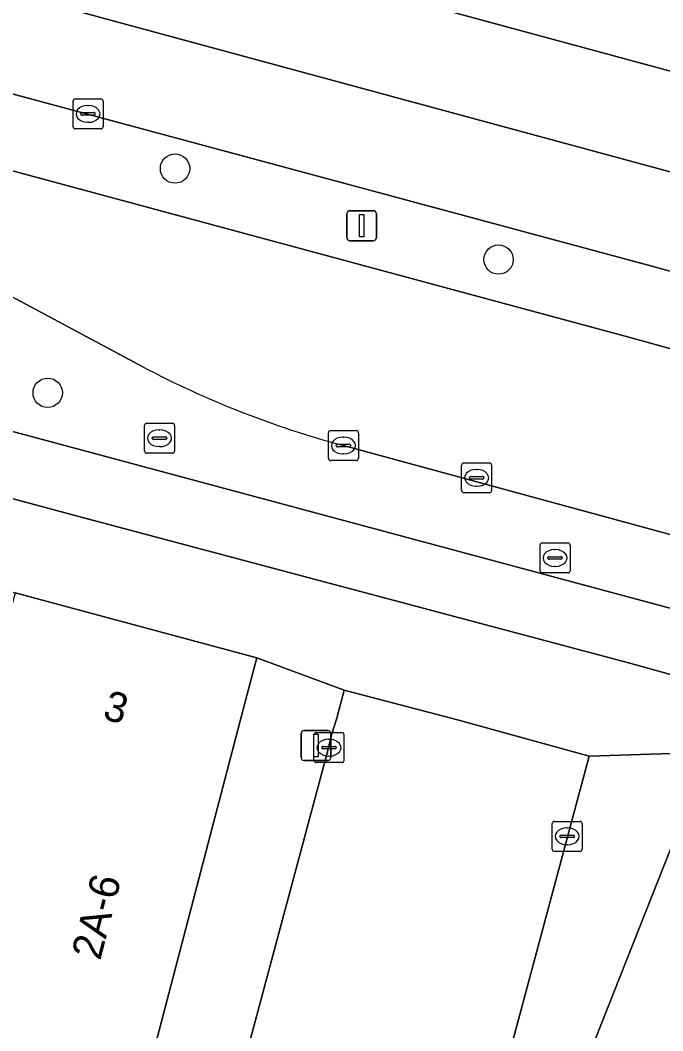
# Model space of a CAD drawing. Extents: x 160675 to 161153, y 383241 to 383714.
# Drawn here: x 160849.57 to 160871.01, y 383553.38 to 383587.08 of the extents above; entities that cross this region are included whole.
import ezdxf

# ---------------------------------------------------------------- set-up
doc = ezdxf.new("R2010")
doc.units = 0
for name, color, linetype in [('IMGEO_Berm_groen', 7, 'Continuous'), ('IMGEO_Berm_open', 7, 'Continuous'), ('IMGEO_Boom', 7, 'Continuous'), ('IMGEO_Fietspad_gesloten', 7, 'Continuous'), ('IMGEO_Kolk', 7, 'Continuous'), ('IMGEO_Lichtmast', 7, 'Continuous'), ('IMGEO_OVBaan_gesloten', 7, 'Continuous'), ('IMGEO_Pand', 7, 'Continuous'), ('IMGEO_Pand_nummerreeks', 7, 'Continuous'), ('IMGEO_Rijbaan_lokaal_gesloten', 7, 'Continuous'), ('IMGEO_Rijbaan_lokaal_open', 7, 'Continuous'), ('IMGEO_Rioolput', 7, 'Continuous'), ('IMGEO_Voetpad_open', 7, 'Continuous')]:
    doc.layers.add(name, color=color, linetype=linetype)

msp = doc.modelspace()

# ---------------------------------------------------------------- linework, layer by layer
at = {"layer": 'IMGEO_Berm_groen'}
for points in [[(160870.684, 383578.867), (160797.835, 383598.49), (160797.171, 383596.125), (160869.874, 383576.512), (160913.282, 383564.496)], [(160946.568, 383557.927), (160870.684, 383578.867)]]:
    msp.add_lwpolyline(points, dxfattribs=at)
at = {"layer": 'IMGEO_Berm_open'}
for points in [[(160753.356, 383599.164), (160754.374, 383598.874), (160872.54, 383567.128), (160873.601, 383566.834), (160874.194, 383569.11), (160871.092, 383569.968), (160860.355, 383572.895)], [(160853.656, 383575.522), (160848.337, 383578.365), (160844.949, 383579.673)]]:
    msp.add_lwpolyline(points, dxfattribs=at)
msp.add_arc((160868.647, 383603.896), 32.091, 242.1503, 255.0247, dxfattribs=at)
at = {"layer": 'IMGEO_Boom'}
for centre in [(160854.735, 383582.13), (160865.529, 383579.098), (160850.486, 383574.652)]:
    msp.add_circle(centre, 0.489, dxfattribs=at)
at = {"layer": 'IMGEO_Fietspad_gesloten'}
for points in [[(160741.54, 383600.127), (160851.652, 383570.489), (160869.912, 383565.633), (160904.417, 383556.04)], [(160904.814, 383558.169), (160877.012, 383565.887), (160875.567, 383566.288), (160873.601, 383566.834), (160872.54, 383567.128), (160754.374, 383598.874)]]:
    msp.add_lwpolyline(points, dxfattribs=at)
at = {"layer": 'IMGEO_Kolk'}
for p, q in [((160851.331, 383583.529), (160851.331, 383584.381)), ((160851.406, 383584.455), (160852.258, 383584.455)), ((160851.819, 383584.235), (160851.844, 383584.235)), ((160852.332, 383584.381), (160852.332, 383583.529)), ((160851.59, 383583.949), (160851.59, 383583.961)), ((160852.028, 383583.912), (160851.63, 383583.912)), ((160851.633, 383583.998), (160852.031, 383583.998)), ((160852.074, 383583.961), (160852.074, 383583.949)), ((160851.842, 383583.675), (160851.817, 383583.675)), ((160852.258, 383583.455), (160851.406, 383583.455)), ((160853.718, 383572.712), (160853.718, 383573.564)), ((160853.793, 383573.638), (160854.645, 383573.638)), ((160854.206, 383573.418), (160854.231, 383573.418)), ((160854.719, 383573.564), (160854.719, 383572.712)), ((160859.929, 383573.394), (160860.781, 383573.394)), ((160853.977, 383573.132), (160853.977, 383573.144)), ((160854.415, 383573.095), (160854.017, 383573.095)), ((160854.02, 383573.181), (160854.418, 383573.181)), ((160854.461, 383573.144), (160854.461, 383573.132)), ((160859.854, 383572.468), (160859.854, 383573.32)), ((160860.342, 383573.174), (160860.367, 383573.174)), ((160860.855, 383573.32), (160860.855, 383572.468)), ((160854.229, 383572.858), (160854.204, 383572.858)), ((160860.113, 383572.888), (160860.113, 383572.9)), ((160860.551, 383572.851), (160860.153, 383572.851)), ((160860.156, 383572.937), (160860.554, 383572.937)), ((160860.597, 383572.9), (160860.597, 383572.888)), ((160854.645, 383572.638), (160853.793, 383572.638)), ((160860.781, 383572.394), (160859.929, 383572.394)), ((160860.365, 383572.614), (160860.34, 383572.614)), ((160859.447, 383563.319), (160860.299, 383563.319)), ((160859.372, 383562.393), (160859.372, 383563.245)), ((160859.86, 383563.099), (160859.885, 383563.099)), ((160860.373, 383563.245), (160860.373, 383562.393)), ((160859.631, 383562.813), (160859.631, 383562.825)), ((160860.069, 383562.776), (160859.671, 383562.776)), ((160859.674, 383562.862), (160860.072, 383562.862)), ((160860.115, 383562.825), (160860.115, 383562.813)), ((160860.299, 383562.319), (160859.447, 383562.319)), ((160859.883, 383562.539), (160859.858, 383562.539)), ((160867.319, 383559.434), (160867.319, 383560.286)), ((160867.394, 383560.36), (160868.246, 383560.36)), ((160868.32, 383560.286), (160868.32, 383559.434)), ((160867.621, 383559.903), (160868.019, 383559.903)), ((160867.807, 383560.14), (160867.832, 383560.14)), ((160867.578, 383559.854), (160867.578, 383559.866)), ((160868.016, 383559.817), (160867.618, 383559.817)), ((160867.83, 383559.58), (160867.805, 383559.58)), ((160868.062, 383559.866), (160868.062, 383559.854)), ((160868.246, 383559.36), (160867.394, 383559.36))]:
    msp.add_line(p, q, dxfattribs=at)
for points in [[(160851.331, 383583.529), (160851.331, 383584.381)], [(160851.406, 383584.455), (160852.258, 383584.455)], [(160852.332, 383584.381), (160852.332, 383583.529)], [(160852.258, 383583.455), (160851.406, 383583.455)], [(160853.718, 383572.712), (160853.718, 383573.564)], [(160853.793, 383573.638), (160854.645, 383573.638)], [(160854.719, 383573.564), (160854.719, 383572.712)], [(160859.929, 383573.394), (160860.781, 383573.394)], [(160859.854, 383572.468), (160859.854, 383573.32)], [(160860.855, 383573.32), (160860.855, 383572.468)], [(160854.645, 383572.638), (160853.793, 383572.638)], [(160860.781, 383572.394), (160859.929, 383572.394)], [(160859.447, 383563.319), (160860.299, 383563.319)], [(160859.372, 383562.393), (160859.372, 383563.245)], [(160860.373, 383563.245), (160860.373, 383562.393)], [(160860.299, 383562.319), (160859.447, 383562.319)], [(160867.319, 383559.434), (160867.319, 383560.286)], [(160867.394, 383560.36), (160868.246, 383560.36)], [(160868.32, 383560.286), (160868.32, 383559.434)], [(160868.246, 383559.36), (160867.394, 383559.36)]]:
    msp.add_lwpolyline(points, dxfattribs=at)
for centre, radius, start, end in [((160851.408, 383584.379), 0.0765, 91.552, 178.448), ((160851.408, 383584.379), 0.0765, 91.552, 178.448), ((160852.256, 383584.379), 0.0765, 1.552, 88.448), ((160852.256, 383584.379), 0.0765, 1.552, 88.448), ((160851.63, 383583.958), 0.0403, 85.8775, 175.7526), ((160851.627, 383583.948), 0.0366, 178.938, 274.7102), ((160852.031, 383583.955), 0.043, 264.8664, 352.4533), ((160852.035, 383583.96), 0.0386, 1.7309, 96.639), ((160851.408, 383583.531), 0.0765, 181.552, 268.448), ((160851.408, 383583.531), 0.0765, 181.552, 268.448), ((160852.256, 383583.531), 0.0765, 271.552, 358.448), ((160852.256, 383583.531), 0.0765, 271.552, 358.448), ((160853.795, 383573.562), 0.0765, 91.552, 178.448), ((160853.795, 383573.562), 0.0765, 91.552, 178.448), ((160854.643, 383573.562), 0.0765, 1.552, 88.448), ((160854.643, 383573.562), 0.0765, 1.552, 88.448), ((160859.931, 383573.318), 0.0765, 91.552, 178.448), ((160859.931, 383573.318), 0.0765, 91.552, 178.448), ((160860.779, 383573.318), 0.0765, 1.552, 88.448), ((160860.779, 383573.318), 0.0765, 1.552, 88.448), ((160854.017, 383573.141), 0.0403, 85.8775, 175.7526), ((160854.014, 383573.131), 0.0366, 178.938, 274.7102), ((160854.418, 383573.138), 0.043, 264.8664, 352.4533), ((160854.422, 383573.143), 0.0386, 1.7309, 96.639), ((160853.795, 383572.714), 0.0765, 181.552, 268.448), ((160853.795, 383572.714), 0.0765, 181.552, 268.448), ((160854.643, 383572.714), 0.0765, 271.552, 358.448), ((160854.643, 383572.714), 0.0765, 271.552, 358.448), ((160860.153, 383572.897), 0.0403, 85.8775, 175.7526), ((160860.15, 383572.887), 0.0366, 178.938, 274.7102), ((160860.554, 383572.894), 0.043, 264.8664, 352.4533), ((160860.558, 383572.899), 0.0386, 1.7309, 96.639), ((160859.931, 383572.47), 0.0765, 181.552, 268.448), ((160859.931, 383572.47), 0.0765, 181.552, 268.448), ((160860.779, 383572.47), 0.0765, 271.552, 358.448), ((160860.779, 383572.47), 0.0765, 271.552, 358.448), ((160859.449, 383563.243), 0.0765, 91.552, 178.448), ((160859.449, 383563.243), 0.0765, 91.552, 178.448), ((160860.297, 383563.243), 0.0765, 1.552, 88.448), ((160860.297, 383563.243), 0.0765, 1.552, 88.448), ((160859.671, 383562.822), 0.0403, 85.8775, 175.7526), ((160859.668, 383562.812), 0.0366, 178.938, 274.7102), ((160860.072, 383562.819), 0.043, 264.8664, 352.4533), ((160860.076, 383562.824), 0.0386, 1.7309, 96.639), ((160859.449, 383562.395), 0.0765, 181.552, 268.448), ((160859.449, 383562.395), 0.0765, 181.552, 268.448), ((160860.297, 383562.395), 0.0765, 271.552, 358.448), ((160860.297, 383562.395), 0.0765, 271.552, 358.448), ((160867.396, 383560.284), 0.0765, 91.552, 178.448), ((160867.396, 383560.284), 0.0765, 91.552, 178.448), ((160868.244, 383560.284), 0.0765, 1.552, 88.448), ((160868.244, 383560.284), 0.0765, 1.552, 88.448), ((160867.618, 383559.863), 0.0403, 85.8775, 175.7526), ((160868.023, 383559.865), 0.0386, 1.7309, 96.639), ((160867.615, 383559.853), 0.0366, 178.938, 274.7102), ((160868.019, 383559.86), 0.043, 264.8664, 352.4533), ((160867.396, 383559.436), 0.0765, 181.552, 268.448), ((160867.396, 383559.436), 0.0765, 181.552, 268.448), ((160868.244, 383559.436), 0.0765, 271.552, 358.448), ((160868.244, 383559.436), 0.0765, 271.552, 358.448)]:
    msp.add_arc(centre, radius, start, end, dxfattribs=at)
for centre, major_axis, ratio, start_param, end_param in [((160851.818, 383583.955), (-0.387, 0.002), 0.722429, 4.712389, 7.853982), ((160851.843, 383583.955), (-0.39, 0.002), 0.717154, 1.570796, 4.712389), ((160854.205, 383573.138), (-0.387, 0.002), 0.722429, 4.712389, 7.853982), ((160854.23, 383573.138), (-0.39, 0.002), 0.717154, 1.570796, 4.712389), ((160860.341, 383572.894), (-0.387, 0.002), 0.722429, 4.712389, 7.853982), ((160860.366, 383572.894), (-0.39, 0.002), 0.717154, 1.570796, 4.712389), ((160859.859, 383562.819), (-0.387, 0.002), 0.722429, 4.712389, 7.853982), ((160859.884, 383562.819), (-0.39, 0.002), 0.717154, 1.570796, 4.712389), ((160867.806, 383559.86), (-0.387, 0.002), 0.722429, 4.712389, 7.853982), ((160867.831, 383559.86), (-0.39, 0.002), 0.717154, 1.570796, 4.712389)]:
    msp.add_ellipse(centre, major_axis=major_axis, ratio=ratio, start_param=start_param, end_param=end_param, dxfattribs=at)
at = {"layer": 'IMGEO_Lichtmast'}
for p, q in [((160860.468, 383579.826), (160860.468, 383580.626)), ((160860.468, 383580.626), (160860.468, 383579.826)), ((160860.568, 383580.726), (160861.358, 383580.726)), ((160861.358, 383580.726), (160860.568, 383580.726)), ((160861.458, 383580.626), (160861.458, 383579.826)), ((160861.458, 383579.826), (160861.458, 383580.626)), ((160861.358, 383579.726), (160860.568, 383579.726)), ((160860.568, 383579.726), (160861.358, 383579.726)), ((160858.942, 383562.49), (160858.942, 383563.29)), ((160858.942, 383563.29), (160858.942, 383562.49)), ((160859.042, 383563.39), (160859.832, 383563.39)), ((160859.832, 383563.39), (160859.042, 383563.39)), ((160859.932, 383563.29), (160859.932, 383562.49)), ((160859.932, 383562.49), (160859.932, 383563.29)), ((160859.832, 383562.39), (160859.042, 383562.39)), ((160859.042, 383562.39), (160859.832, 383562.39))]:
    msp.add_line(p, q, dxfattribs=at)
for points in [[(160860.888, 383580.601), (160861.038, 383580.601), (160861.038, 383579.851), (160860.888, 383579.851), (160860.888, 383580.601)], [(160859.362, 383563.265), (160859.512, 383563.265), (160859.512, 383562.515), (160859.362, 383562.515), (160859.362, 383563.265)]]:
    msp.add_lwpolyline(points, dxfattribs=at)
for centre, start, end in [((160860.568, 383580.626), 90, 180), ((160860.568, 383580.626), 90, 180), ((160861.358, 383580.626), 0, 90), ((160861.358, 383580.626), 360, 90), ((160860.568, 383579.826), 180, 270), ((160860.568, 383579.826), 180, 270), ((160861.358, 383579.826), 270, 0), ((160861.358, 383579.826), 270, 0), ((160859.042, 383563.29), 90, 180), ((160859.042, 383563.29), 90, 180), ((160859.832, 383563.29), 0, 90), ((160859.832, 383563.29), 360, 90), ((160859.042, 383562.49), 180, 270), ((160859.042, 383562.49), 180, 270), ((160859.832, 383562.49), 270, 0), ((160859.832, 383562.49), 270, 0)]:
    msp.add_arc(centre, 0.1, start, end, dxfattribs=at)
at = {"layer": 'IMGEO_OVBaan_gesloten'}
for points in [[(160760.567, 383616.024), (160759.368, 383616.453), (160756.884, 383613.99), (160761.763, 383612.059), (160766.781, 383610.37), (160770.415, 383609.332), (160774.938, 383608.123), (160890.249, 383576.873), (160942.076, 383562.592), (160950.815, 383560.255), (160956.785, 383559.216), (160962.841, 383558.697), (160968.725, 383558.524), (160975.387, 383558.61), (160977.148, 383558.794), (160977.505, 383562.304), (160973.835, 383561.901)], [(160973.434, 383555.262), (160976.812, 383555.49), (160977.148, 383558.794), (160975.387, 383558.61), (160968.725, 383558.524), (160962.841, 383558.697), (160956.785, 383559.216), (160950.815, 383560.255), (160942.076, 383562.592), (160890.249, 383576.873), (160774.938, 383608.123), (160770.415, 383609.332), (160766.781, 383610.37), (160761.763, 383612.059), (160756.884, 383613.99)], [(160949.177, 383564.05), (160942.127, 383565.955), (160880.388, 383583.018), (160880.346, 383582.924), (160861.613, 383588.006), (160783.094, 383609.33)], [(160765.95, 383607.15), (160797.835, 383598.49), (160870.684, 383578.867), (160946.568, 383557.927)]]:
    msp.add_lwpolyline(points, dxfattribs=at)
at = {"layer": 'IMGEO_Pand'}
msp.add_lwpolyline([(160857.143, 383564.601), (160857.461, 383565.816), (160849.404, 383567.986), (160845.929, 383555.083), (160845.578, 383553.78), (160844.825, 383550.984), (160843.174, 383544.853), (160849.994, 383543.081), (160850.028, 383543.072), (160850.324, 383542.913), (160852.917, 383548.465)], close=True, dxfattribs=at)
at = {"layer": 'IMGEO_Rijbaan_lokaal_gesloten'}
for points in [[(160784.127, 383609.308), (160809.68, 383602.419), (160845.226, 383592.848), (160861.742, 383588.359), (160861.613, 383588.006), (160880.346, 383582.924), (160880.388, 383583.018), (160880.432, 383583.23), (160883.368, 383582.463), (160942.181, 383566.161)], [(160748.774, 383605.431), (160752.694, 383604.486), (160754.68, 383603.938), (160760.442, 383602.399), (160762.407, 383601.874), (160786.733, 383595.326), (160792.524, 383593.731), (160819.386, 383586.497), (160826.28, 383584.667), (160844.949, 383579.673), (160848.337, 383578.365), (160853.656, 383575.522)], [(160869.874, 383576.512), (160797.171, 383596.125), (160768.531, 383603.87)], [(160913.282, 383564.496), (160869.874, 383576.512)], [(160860.355, 383572.895), (160871.092, 383569.968), (160874.194, 383569.11), (160876.194, 383568.556), (160877.64, 383568.157), (160899.725, 383562.047), (160911.387, 383558.791)]]:
    msp.add_lwpolyline(points, dxfattribs=at)
msp.add_arc((160868.647, 383603.896), 32.091, 242.1503, 255.0247, dxfattribs=at)
at = {"layer": 'IMGEO_Rijbaan_lokaal_open'}
msp.add_lwpolyline([(160862.182, 383538.869), (160865.424, 383550.899), (160868.559, 383562.537), (160864.165, 383563.744), (160860.38, 383564.733), (160860.129, 383563.804), (160859.957, 383563.251), (160859.831, 383562.723), (160856.929, 383551.908)], dxfattribs=at)
at = {"layer": 'IMGEO_Rioolput'}
for p, q in [((160864.299, 383571.392), (160864.299, 383572.244)), ((160864.374, 383572.318), (160865.226, 383572.318)), ((160864.787, 383572.098), (160864.812, 383572.098)), ((160865.3, 383572.244), (160865.3, 383571.392)), ((160864.558, 383571.812), (160864.558, 383571.824)), ((160864.996, 383571.775), (160864.598, 383571.775)), ((160864.601, 383571.861), (160864.999, 383571.861)), ((160865.042, 383571.824), (160865.042, 383571.812)), ((160864.81, 383571.538), (160864.785, 383571.538)), ((160865.226, 383571.318), (160864.374, 383571.318)), ((160866.914, 383568.719), (160866.914, 383569.571)), ((160866.989, 383569.645), (160867.841, 383569.645)), ((160867.402, 383569.425), (160867.427, 383569.425)), ((160867.915, 383569.571), (160867.915, 383568.719)), ((160867.173, 383569.139), (160867.173, 383569.151)), ((160867.611, 383569.102), (160867.213, 383569.102)), ((160867.216, 383569.188), (160867.614, 383569.188)), ((160867.657, 383569.151), (160867.657, 383569.139)), ((160867.425, 383568.865), (160867.4, 383568.865)), ((160867.841, 383568.645), (160866.989, 383568.645))]:
    msp.add_line(p, q, dxfattribs=at)
for points in [[(160864.299, 383571.392), (160864.299, 383572.244)], [(160864.374, 383572.318), (160865.226, 383572.318)], [(160865.3, 383572.244), (160865.3, 383571.392)], [(160865.226, 383571.318), (160864.374, 383571.318)], [(160866.914, 383568.719), (160866.914, 383569.571)], [(160866.989, 383569.645), (160867.841, 383569.645)], [(160867.915, 383569.571), (160867.915, 383568.719)], [(160867.841, 383568.645), (160866.989, 383568.645)]]:
    msp.add_lwpolyline(points, dxfattribs=at)
for centre, radius, start, end in [((160864.376, 383572.242), 0.0765, 91.552, 178.448), ((160864.376, 383572.242), 0.0765, 91.552, 178.448), ((160865.224, 383572.242), 0.0765, 1.552, 88.448), ((160865.224, 383572.242), 0.0765, 1.552, 88.448), ((160864.598, 383571.821), 0.0403, 85.8775, 175.7526), ((160864.595, 383571.811), 0.0366, 178.938, 274.7102), ((160864.999, 383571.818), 0.043, 264.8664, 352.4533), ((160865.003, 383571.823), 0.0386, 1.7309, 96.639), ((160864.376, 383571.394), 0.0765, 181.552, 268.448), ((160864.376, 383571.394), 0.0765, 181.552, 268.448), ((160865.224, 383571.394), 0.0765, 271.552, 358.448), ((160865.224, 383571.394), 0.0765, 271.552, 358.448), ((160866.991, 383569.569), 0.0765, 91.552, 178.448), ((160866.991, 383569.569), 0.0765, 91.552, 178.448), ((160867.839, 383569.569), 0.0765, 1.552, 88.448), ((160867.839, 383569.569), 0.0765, 1.552, 88.448), ((160867.213, 383569.148), 0.0403, 85.8775, 175.7526), ((160867.21, 383569.138), 0.0366, 178.938, 274.7102), ((160867.614, 383569.145), 0.043, 264.8664, 352.4533), ((160867.618, 383569.15), 0.0386, 1.7309, 96.639), ((160866.991, 383568.721), 0.0765, 181.552, 268.448), ((160866.991, 383568.721), 0.0765, 181.552, 268.448), ((160867.839, 383568.721), 0.0765, 271.552, 358.448), ((160867.839, 383568.721), 0.0765, 271.552, 358.448)]:
    msp.add_arc(centre, radius, start, end, dxfattribs=at)
for centre, major_axis, ratio, start_param, end_param in [((160864.786, 383571.818), (-0.387, 0.002), 0.722429, 4.712389, 7.853982), ((160864.811, 383571.818), (-0.39, 0.002), 0.717154, 1.570796, 4.712389), ((160867.401, 383569.145), (-0.387, 0.002), 0.722429, 4.712389, 7.853982), ((160867.426, 383569.145), (-0.39, 0.002), 0.717154, 1.570796, 4.712389)]:
    msp.add_ellipse(centre, major_axis=major_axis, ratio=ratio, start_param=start_param, end_param=end_param, dxfattribs=at)
at = {"layer": 'IMGEO_Voetpad_open'}
for points in [[(160851.652, 383570.489), (160741.54, 383600.127)], [(160818.982, 383576.181), (160825.065, 383574.542), (160831.149, 383572.903), (160837.232, 383571.265), (160843.316, 383569.626), (160849.404, 383567.986), (160857.461, 383565.816), (160860.38, 383564.733), (160864.165, 383563.744), (160868.559, 383562.537), (160871.974, 383562.641), (160891.519, 383557.192), (160898.038, 383555.497), (160905.919, 383553.429)], [(160904.417, 383556.04), (160869.912, 383565.633), (160851.652, 383570.489)], [(160859.831, 383562.723), (160859.957, 383563.251), (160860.129, 383563.804), (160860.38, 383564.733), (160857.461, 383565.816), (160857.143, 383564.601), (160852.917, 383548.465), (160850.324, 383542.913), (160850.028, 383543.072), (160849.994, 383543.081), (160849.734, 383542.418), (160850.083, 383542.287)], [(160856.929, 383551.908), (160859.831, 383562.723)], [(160871.287, 383559.494), (160871.974, 383562.641), (160868.559, 383562.537), (160865.424, 383550.899), (160862.182, 383538.869)], [(160861.525, 383537.121), (160855.717, 383527.187), (160854.143, 383524.612), (160853.325, 383523.422), (160853.08, 383523.019), (160852.899, 383522.475), (160851.327, 383517.544), (160850.446, 383514.813), (160850.389, 383514.634), (160857.402, 383512.924), (160862.229, 383530.692), (160867.046, 383548.766), (160871.287, 383559.494)]]:
    msp.add_lwpolyline(points, dxfattribs=at)
msp.add_lwpolyline([(160898.038, 383555.497), (160891.519, 383557.192), (160891.007, 383554.995), (160871.287, 383559.494), (160867.046, 383548.766), (160882.765, 383552.718), (160882.404, 383551.516), (160882.162, 383550.698), (160884.116, 383550.123), (160884.791, 383552.362), (160884.968, 383552.305), (160888.011, 383551.386), (160888.68, 383551.214), (160889.801, 383546.379), (160890.032, 383546.434), (160895.926, 383547.834), (160895.929, 383547.835), (160897.119, 383552.158), (160897.457, 383553.323)], close=True, dxfattribs=at)

# ---------------------------------------------------------------- texts
at = {"layer": 'IMGEO_Pand_nummerreeks'}
for s, rotation, p in [('3', 344.6046, (160852.282, 383563.788)), ('2A-6', 75.5101, (160852.237, 383555.697))]:
    msp.add_text(s, height=1, rotation=rotation, dxfattribs=at).set_placement(p)

doc.saveas('drawing.dxf')
